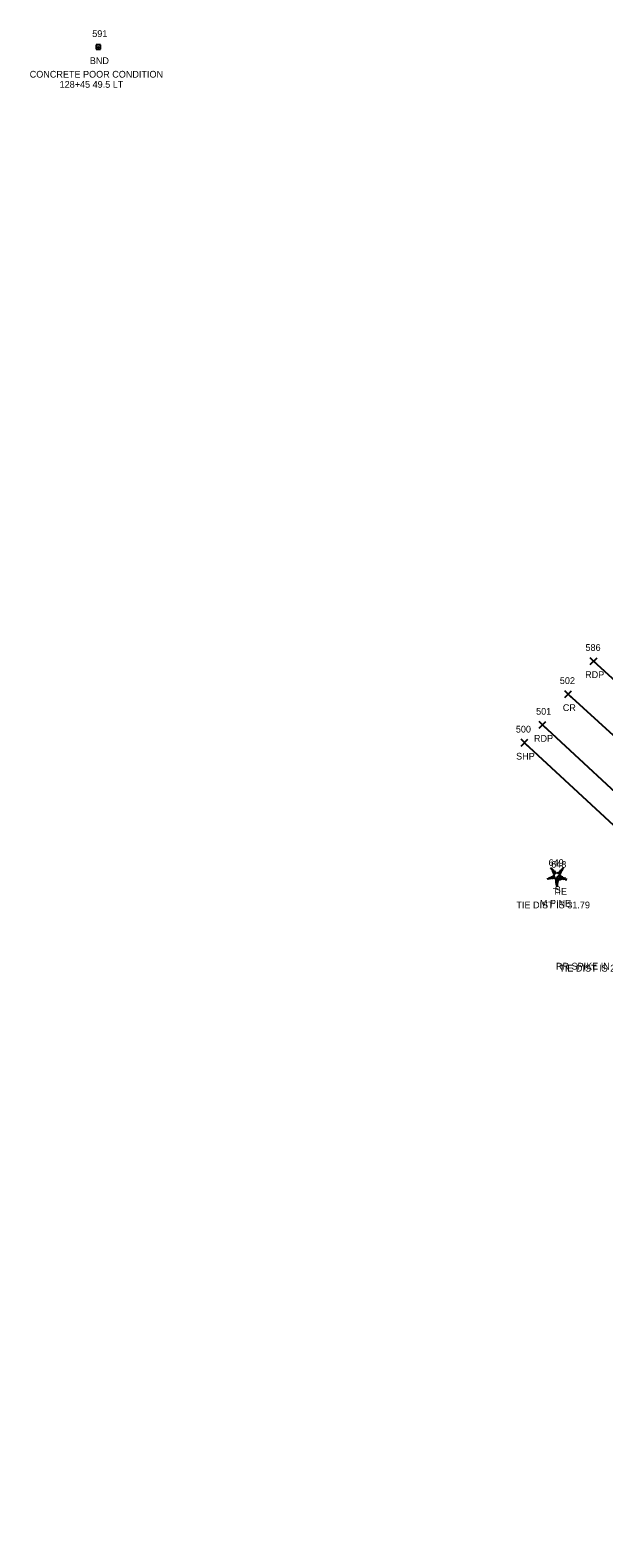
# Model space of a CAD drawing. Extents: x 1611034 to 1613847, y 761049 to 763902.
# Drawn here: x 1611591.7 to 1611761.1, y 762931.8 to 763377.2 of the extents above; entities that cross this region are included whole.
import ezdxf

# ---------------------------------------------------------------- set-up
doc = ezdxf.new("R2010")
doc.units = 0
for name, color, linetype in [('C_A', 7, 'Continuous'), ('C_C', 7, 'Continuous'), ('C_I', 7, 'Continuous'), ('CBP', 7, 'Continuous'), ('L_A', 7, 'Continuous'), ('L_C', 7, 'Continuous'), ('L_I', 7, 'Continuous'), ('Level 18', 7, 'Continuous'), ('LTC', 7, 'Continuous'), ('M_A', 7, 'Continuous'), ('M_C', 7, 'Continuous'), ('M_I', 7, 'Continuous'), ('P_A', 7, 'Continuous'), ('P_I', 7, 'Continuous'), ('P_TIC', 7, 'Continuous'), ('PET', 7, 'Continuous'), ('PRC', 7, 'Continuous'), ('PSP', 7, 'Continuous')]:
    doc.layers.add(name, color=color, linetype=linetype)

msp = doc.modelspace()

# ---------------------------------------------------------------- linework, layer by layer
at = {"layer": 'CBP'}
for radius in [0.625, 0.0833]:
    msp.add_circle((1611747.95, 763126.75), radius, dxfattribs=at)
at = {"layer": 'Level 18'}
for p, q in [((1611612.48, 763372.8), (1611611.23, 763372.8)), ((1611611.23, 763372.8), (1611611.23, 763371.55)), ((1611612.48, 763372.8), (1611611.23, 763372.8)), ((1611611.23, 763372.8), (1611611.23, 763371.55)), ((1611612.48, 763371.55), (1611612.48, 763372.8)), ((1611612.48, 763371.55), (1611612.48, 763372.8)), ((1611611.23, 763371.55), (1611612.48, 763371.55)), ((1611611.23, 763371.55), (1611612.48, 763371.55))]:
    msp.add_line(p, q, dxfattribs=at)
msp.add_circle((1611611.83, 763372.14), 0.0833, dxfattribs=at)
at = {"layer": 'LTC'}
for p, q in [((1611745.37, 763129.46), (1611745.72, 763129.72)), ((1611745.58, 763129), (1611746.11, 763129.38)), ((1611745.79, 763128.53), (1611746.49, 763129.04)), ((1611746, 763128.06), (1611746.88, 763128.7)), ((1611746.22, 763127.61), (1611747.23, 763128.34)), ((1611747.23, 763128.34), (1611748.23, 763127.62)), ((1611747.65, 763128.66), (1611748.46, 763128.07)), ((1611748.02, 763129.01), (1611748.7, 763128.51)), ((1611748.4, 763129.35), (1611748.94, 763128.95)), ((1611748.77, 763129.7), (1611749.19, 763129.4)), ((1611744.4, 763126.74), (1611744.55, 763126.27)), ((1611744.86, 763126.96), (1611745.07, 763126.31)), ((1611745.31, 763127.17), (1611745.58, 763126.34)), ((1611745.77, 763127.39), (1611746.1, 763126.37)), ((1611746.22, 763127.61), (1611746.61, 763126.42)), ((1611747.84, 763126.42), (1611746.61, 763126.42)), ((1611747.8, 763125.92), (1611746.66, 763125.92)), ((1611747.72, 763125.42), (1611746.73, 763125.42)), ((1611747.63, 763124.92), (1611746.8, 763124.92)), ((1611747.55, 763124.42), (1611746.87, 763124.42)), ((1611748.23, 763127.62), (1611747.84, 763126.42)), ((1611748.67, 763127.35), (1611748.33, 763126.31)), ((1611749.11, 763127.1), (1611748.82, 763126.21)), ((1611749.56, 763126.85), (1611749.32, 763126.12)), ((1611750, 763126.6), (1611749.81, 763126.02))]:
    msp.add_line(p, q, dxfattribs=at)
at = {"layer": 'P_TIC'}
for points in [[(1611757.07, 763189.79), (1611759.07, 763191.79)], [(1611759.07, 763189.79), (1611757.07, 763191.79)], [(1611749.53, 763180.03), (1611751.53, 763182.03)], [(1611751.53, 763180.03), (1611749.53, 763182.03)], [(1611741.95, 763170.95), (1611743.95, 763172.95)], [(1611743.95, 763170.95), (1611741.95, 763172.95)], [(1611736.63, 763165.68), (1611738.63, 763167.68)], [(1611738.63, 763165.68), (1611736.63, 763167.68)]]:
    msp.add_lwpolyline(points, dxfattribs=at)
at = {"layer": 'PET'}
for points in [[(1612007.41, 762953.69), (1611981.88, 762978.72), (1611953.4, 763007), (1611921.8, 763038.1), (1611897.05, 763061.61), (1611875.73, 763082.09), (1611849.32, 763106.5), (1611830.38, 763124.18), (1611806.13, 763146.18), (1611781.49, 763169.41), (1611758.07, 763190.79)], [(1611742.95, 763171.95), (1611773.98, 763143.16), (1611800.57, 763118.45), (1611832.55, 763088.78), (1611862.37, 763060.94), (1611895.49, 763029.35), (1611927.37, 762998.83), (1611963.34, 762963.21), (1611989.07, 762936.88)]]:
    msp.add_lwpolyline(points, dxfattribs=at)
at = {"layer": 'PRC'}
msp.add_lwpolyline([(1611750.53, 763181.03), (1611781.55, 763152.75), (1611808.47, 763127.7), (1611840.68, 763098.05), (1611871.03, 763069.71), (1611903.68, 763038.16), (1611935.64, 763007.53), (1611970.73, 762973.2), (1611998.37, 762945.17)], dxfattribs=at)
at = {"layer": 'PSP'}
msp.add_lwpolyline([(1611737.63, 763166.68), (1611769.14, 763137.5), (1611795.96, 763113), (1611827.31, 763083.61), (1611857.87, 763055.56), (1611890.74, 763023.79), (1611921.91, 762994.17), (1611958.53, 762957.84), (1611984.49, 762931.79)], dxfattribs=at)

# ---------------------------------------------------------------- texts
at = {"layer": 'C_A'}
msp.add_text('TIE', height=2, dxfattribs=at).set_placement((1611746.03, 763121.75))
at = {"layer": 'C_C'}
for s, p in [('TIE DIST IS 31.79', (1611735.27, 763117.75)), ('RR SPIKE IN ROOT SMALL PINE', (1611746.93, 763099.66)), ('TIE DIST IS 26.10 IN BM TREE', (1611747.94, 763099.07))]:
    msp.add_text(s, height=2, dxfattribs=at).set_placement(p)
at = {"layer": 'C_I'}
msp.add_text('648', height=2, dxfattribs=at).set_placement((1611745.54, 763129.75))
at = {"layer": 'L_A'}
msp.add_text('S', height=2, dxfattribs=at).set_placement((1611746.56, 763122.25))
at = {"layer": 'L_C'}
msp.add_text('M PINE', height=2, dxfattribs=at).set_placement((1611742.2, 763118.25))
at = {"layer": 'L_I'}
msp.add_text('649', height=2, dxfattribs=at).set_placement((1611744.76, 763130.25))
at = {"layer": 'LTC'}
msp.add_text('.', height=1.04, rotation=270, dxfattribs=at).set_placement((1611747.12, 763127.36))
at = {"layer": 'M_A'}
msp.add_text('BND', height=2, dxfattribs=at).set_placement((1611609.32, 763367.15))
at = {"layer": 'M_C'}
for s, p in [('CONCRETE POOR CONDITION', (1611591.57, 763363.15)), ('128+45 49.5 LT', (1611600.4, 763360.15))]:
    msp.add_text(s, height=2, dxfattribs=at).set_placement(p)
at = {"layer": 'M_I'}
msp.add_text('591', height=2, dxfattribs=at).set_placement((1611610.03, 763375.15))
at = {"layer": 'P_A'}
for s, p in [('RDP', (1611755.56, 763185.79)), ('CR', (1611748.96, 763176.03)), ('RDP', (1611740.44, 763166.95)), ('SHP', (1611735.17, 763161.68))]:
    msp.add_text(s, height=2, dxfattribs=at).set_placement(p)
at = {"layer": 'P_I'}
for s, p in [('586', (1611755.66, 763193.79)), ('502', (1611748.09, 763184.03)), ('501', (1611741.08, 763174.95)), ('500', (1611735.1, 763169.68))]:
    msp.add_text(s, height=2, dxfattribs=at).set_placement(p)

doc.saveas('drawing.dxf')
